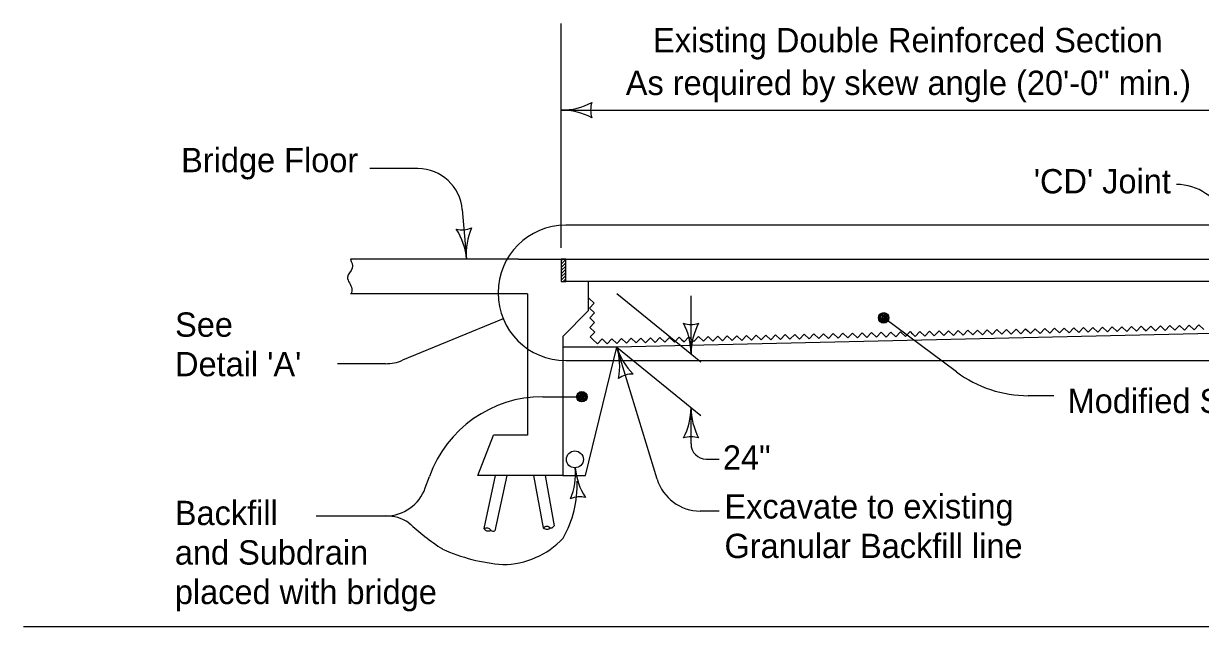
# Model space of a CAD drawing. Extents: x -2134860 to -2124557, y -2139046 to -2137324.
# Drawn here: x -2131334 to -2130560, y -2138041 to -2137644 of the extents above; entities that cross this region are included whole.
import ezdxf

# ---------------------------------------------------------------- set-up
doc = ezdxf.new("R2010")
doc.units = 0
for name, color, linetype in [('BridgeSuperStructureExisting', 7, 'Continuous'), ('dsnAlignmentCurveData', 7, 'Continuous'), ('dsnStdLabel', 7, 'Continuous')]:
    doc.layers.add(name, color=color, linetype=linetype)

msp = doc.modelspace()

# ---------------------------------------------------------------- linework, layer by layer
at = {"layer": 'BridgeSuperStructureExisting'}
for p, q in [((-2130980.5, -2137791.68), (-2130980.5, -2137644.1)), ((-2130980.5, -2137701.07), (-2130532.03, -2137701.07)), ((-2131074.8, -2137739.48), (-2131106.53, -2137739.48)), ((-2131045.68, -2137766.6), (-2131042.85, -2137799.1)), ((-2130172.43, -2137776.83), (-2130977.53, -2137776.83)), ((-2131008.72, -2137799.1), (-2131119.33, -2137799.1)), ((-2131008.72, -2137799.1), (-2130980.5, -2137799.1)), ((-2130980.5, -2137799.1), (-2130980.5, -2137813.91)), ((-2130977.53, -2137799.1), (-2130980.5, -2137799.1)), ((-2130980.5, -2137802.48), (-2130977.53, -2137799.51)), ((-2130980.5, -2137800.38), (-2130979.63, -2137799.51)), ((-2130977.53, -2137799.51), (-2130980.5, -2137799.51)), ((-2130977.53, -2137799.1), (-2129819.23, -2137799.1)), ((-2130980.5, -2137804.58), (-2130977.53, -2137801.61)), ((-2130980.5, -2137806.68), (-2130977.53, -2137803.71)), ((-2130980.5, -2137808.78), (-2130977.53, -2137805.81)), ((-2130980.5, -2137810.88), (-2130977.53, -2137807.91)), ((-2130980.5, -2137812.98), (-2130977.53, -2137810.01)), ((-2130980.5, -2137813.91), (-2130977.53, -2137813.91)), ((-2130979.33, -2137813.91), (-2130977.53, -2137812.11)), ((-2129819.23, -2137813.95), (-2130977.53, -2137813.95)), ((-2130962.68, -2137813.91), (-2130962.68, -2137833.26)), ((-2131002.78, -2137822.01), (-2131119.33, -2137822.01)), ((-2131002.78, -2137822.01), (-2131002.78, -2137914.93)), ((-2130943.89, -2137821.73), (-2130888.61, -2137866.75)), ((-2130895.08, -2137861.48), (-2130895.08, -2137823.29)), ((-2129819.23, -2137831.61), (-2130943.89, -2137857.02)), ((-2131018.7, -2137838.39), (-2131084.89, -2137865.74)), ((-2130962.68, -2137833.26), (-2130979.48, -2137850.06)), ((-2130720.28, -2137873.45), (-2130768.25, -2137837.85)), ((-2130979.48, -2137850.06), (-2130979.48, -2137941.66)), ((-2130943.89, -2137857.02), (-2130979.48, -2137857.02)), ((-2130964.58, -2137941.66), (-2130943.89, -2137857.02)), ((-2130943.89, -2137857.02), (-2130888.61, -2137902.04)), ((-2130917.41, -2137943.9), (-2130943.89, -2137857.02)), ((-2131096.23, -2137867.99), (-2131127.79, -2137867.99)), ((-2130977.53, -2137865.93), (-2130172.43, -2137865.93)), ((-2130656.21, -2137889.05), (-2130673.08, -2137889.05)), ((-2130895.08, -2137920.77), (-2130895.08, -2137896.77)), ((-2131035.45, -2137941.66), (-2131025.17, -2137914.93)), ((-2131002.78, -2137914.93), (-2131025.17, -2137914.93)), ((-2130885.08, -2137930.77), (-2130876.52, -2137930.77)), ((-2130979.48, -2137941.66), (-2131035.45, -2137941.66)), ((-2131023.98, -2137941.66), (-2131031.49, -2137976.48)), ((-2131016.39, -2137941.66), (-2131024.24, -2137978.05)), ((-2130998.72, -2137941.66), (-2130992.42, -2137976)), ((-2130991.17, -2137941.66), (-2130985.11, -2137974.66)), ((-2130979.48, -2137941.66), (-2130964.58, -2137941.66)), ((-2130889, -2137964.94), (-2130876.52, -2137964.94))]:
    msp.add_line(p, q, dxfattribs=at)
for points in [[(-2130959.72, -2137852.08), (-2130961.45, -2137850.42), (-2130958.36, -2137847.18), (-2130961.6, -2137844.08), (-2130958.51, -2137840.84), (-2130961.75, -2137837.75), (-2130958.66, -2137834.51), (-2130961.9, -2137831.42), (-2130958.8, -2137828.17), (-2130962.04, -2137825.08), (-2130961.9, -2137824.93)], [(-2130767.99, -2137834.67), (-2130769.15, -2137835.19), (-2130770.97, -2137835.76), (-2130771.33, -2137837.6), (-2130771.08, -2137839.22), (-2130769.91, -2137840.72), (-2130768.18, -2137840.57), (-2130766.36, -2137840.31), (-2130765.48, -2137838.86), (-2130765.32, -2137837.33), (-2130766.4, -2137835.32), (-2130767.73, -2137835.15), (-2130769.55, -2137835.62), (-2130771.04, -2137836.78), (-2130770.99, -2137838.51), (-2130769.83, -2137839.9), (-2130768.2, -2137840.06), (-2130766.37, -2137839.7), (-2130766.09, -2137838.68), (-2130765.73, -2137837.44), (-2130766.59, -2137835.94), (-2130767.91, -2137835.97), (-2130769.43, -2137836.22), (-2130770.53, -2137837.07), (-2130769.97, -2137838.58), (-2130768.83, -2137839.47), (-2130767.29, -2137839.52), (-2130766.91, -2137838.7), (-2130766.43, -2137837.76), (-2130767.18, -2137836.57), (-2130768.3, -2137836.29), (-2130769.31, -2137836.83), (-2130769.38, -2137837.95), (-2130768.85, -2137838.75), (-2130767.82, -2137839.03), (-2130767.32, -2137838.6), (-2130767.03, -2137837.99), (-2130767.57, -2137837.08), (-2130768.29, -2137836.9), (-2130768.99, -2137837.33), (-2130768.87, -2137837.94), (-2130768.35, -2137838.33), (-2130767.64, -2137838.31), (-2130767.65, -2137837.8), (-2130768.27, -2137837.51)], [(-2130825.23, -2137850.23), (-2130823.61, -2137851.78), (-2130820.51, -2137848.54), (-2130817.27, -2137851.62), (-2130814.18, -2137848.39), (-2130810.94, -2137851.47), (-2130807.85, -2137848.24), (-2130804.6, -2137851.33), (-2130801.51, -2137848.09), (-2130798.27, -2137851.18), (-2130795.18, -2137847.94), (-2130791.94, -2137851.03), (-2130788.84, -2137847.79), (-2130785.6, -2137850.88), (-2130782.51, -2137847.64), (-2130779.27, -2137850.74), (-2130776.18, -2137847.5), (-2130772.93, -2137850.59), (-2130769.84, -2137847.35), (-2130766.6, -2137850.44), (-2130763.51, -2137847.2), (-2130760.27, -2137850.29), (-2130757.17, -2137847.05), (-2130753.93, -2137850.14), (-2130750.84, -2137846.9), (-2130749.22, -2137848.45)], [(-2130749.22, -2137848.44), (-2130747.6, -2137849.99), (-2130744.51, -2137846.75), (-2130741.26, -2137849.84), (-2130738.17, -2137846.6), (-2130734.93, -2137849.69), (-2130731.83, -2137846.45), (-2130728.59, -2137849.54), (-2130725.5, -2137846.3), (-2130722.26, -2137849.39), (-2130719.17, -2137846.15), (-2130715.93, -2137849.25), (-2130712.83, -2137846), (-2130709.59, -2137849.1), (-2130706.5, -2137845.86), (-2130703.26, -2137848.95), (-2130700.17, -2137845.71), (-2130696.92, -2137848.8), (-2130693.83, -2137845.56), (-2130690.59, -2137848.65), (-2130687.5, -2137845.41), (-2130684.26, -2137848.5), (-2130681.16, -2137845.26), (-2130677.92, -2137848.35), (-2130674.82, -2137845.11), (-2130673.21, -2137846.66)], [(-2130673.21, -2137846.65), (-2130671.59, -2137848.2), (-2130668.5, -2137844.96), (-2130665.25, -2137848.05), (-2130662.16, -2137844.81), (-2130658.92, -2137847.91), (-2130655.83, -2137844.66), (-2130652.59, -2137847.76), (-2130649.49, -2137844.51), (-2130646.25, -2137847.61), (-2130643.16, -2137844.37), (-2130639.91, -2137847.46), (-2130636.83, -2137844.22), (-2130633.58, -2137847.31), (-2130630.49, -2137844.07), (-2130627.25, -2137847.17), (-2130624.15, -2137843.92), (-2130620.91, -2137847.02), (-2130617.82, -2137843.77), (-2130614.58, -2137846.86), (-2130611.49, -2137843.63), (-2130608.24, -2137846.72), (-2130605.15, -2137843.48), (-2130601.91, -2137846.57), (-2130598.82, -2137843.33), (-2130597.19, -2137844.88)], [(-2130597.19, -2137844.9), (-2130595.57, -2137846.45), (-2130592.48, -2137843.2), (-2130589.24, -2137846.3), (-2130586.15, -2137843.06), (-2130582.91, -2137846.14), (-2130579.81, -2137842.9), (-2130576.57, -2137846), (-2130573.48, -2137842.75), (-2130570.24, -2137845.85), (-2130567.15, -2137842.61), (-2130563.9, -2137845.7), (-2130560.81, -2137842.46), (-2130557.57, -2137845.55)], [(-2130959.94, -2137851.95), (-2130959.87, -2137851.87), (-2130956.63, -2137854.97), (-2130953.53, -2137851.72), (-2130950.29, -2137854.82), (-2130947.2, -2137851.58), (-2130943.96, -2137854.67), (-2130940.87, -2137851.43), (-2130937.62, -2137854.52), (-2130934.53, -2137851.28), (-2130931.29, -2137854.37), (-2130928.2, -2137851.13), (-2130924.96, -2137854.22), (-2130921.86, -2137850.98), (-2130918.62, -2137854.07), (-2130915.53, -2137850.83), (-2130912.29, -2137853.93), (-2130909.19, -2137850.69), (-2130905.95, -2137853.78), (-2130902.86, -2137850.54), (-2130901.24, -2137852.08)], [(-2130901.24, -2137852.01), (-2130899.62, -2137853.56), (-2130896.53, -2137850.32), (-2130893.28, -2137853.42), (-2130890.19, -2137850.17), (-2130886.95, -2137853.26), (-2130883.86, -2137850.03), (-2130880.62, -2137853.11), (-2130877.52, -2137849.87), (-2130874.28, -2137852.96), (-2130871.19, -2137849.72), (-2130867.95, -2137852.82), (-2130864.86, -2137849.58), (-2130861.61, -2137852.67), (-2130858.52, -2137849.43), (-2130855.28, -2137852.52), (-2130852.19, -2137849.28), (-2130848.95, -2137852.37), (-2130845.85, -2137849.13), (-2130842.61, -2137852.23), (-2130839.52, -2137848.99), (-2130836.27, -2137852.08), (-2130833.18, -2137848.84), (-2130829.94, -2137851.93), (-2130826.85, -2137848.69), (-2130825.23, -2137850.24)], [(-2130967.21, -2137892.91), (-2130966.04, -2137892.38), (-2130964.22, -2137891.82), (-2130963.87, -2137889.97), (-2130964.12, -2137888.35), (-2130965.28, -2137886.86), (-2130967.01, -2137887.01), (-2130968.84, -2137887.26), (-2130969.71, -2137888.72), (-2130969.87, -2137890.25), (-2130968.79, -2137892.26), (-2130967.46, -2137892.42), (-2130965.64, -2137891.96), (-2130964.15, -2137890.8), (-2130964.2, -2137889.07), (-2130965.36, -2137887.68), (-2130967, -2137887.52), (-2130968.82, -2137887.87), (-2130969.09, -2137888.9), (-2130969.47, -2137890.14), (-2130968.61, -2137891.64), (-2130967.28, -2137891.6), (-2130965.76, -2137891.35), (-2130964.67, -2137890.51), (-2130965.22, -2137888.99), (-2130966.37, -2137888.11), (-2130967.9, -2137888.06), (-2130968.28, -2137888.88), (-2130968.76, -2137889.81), (-2130968.02, -2137891.01), (-2130966.89, -2137891.29), (-2130965.88, -2137890.75), (-2130965.82, -2137889.62), (-2130966.35, -2137888.82), (-2130967.38, -2137888.55), (-2130967.87, -2137888.97), (-2130968.16, -2137889.59), (-2130967.62, -2137890.49), (-2130966.9, -2137890.67), (-2130966.2, -2137890.25), (-2130966.32, -2137889.64), (-2130966.85, -2137889.24), (-2130967.56, -2137889.27), (-2130967.54, -2137889.77), (-2130966.92, -2137890.06)]]:
    msp.add_lwpolyline(points, dxfattribs=at)
for centre, radius in [((-2130768.25, -2137837.85), 3.46), ((-2130966.94, -2137889.73), 3.46), ((-2130971.53, -2137930.97), 5.57)]:
    msp.add_circle(centre, radius, dxfattribs=at)
for centre, radius, start, end in [((-2130980.5, -2137658.33), 42.75, 270, 298.07249), ((-2130944.66, -2137701.08), 16.51, 162.26665, 197.73335), ((-2130980.5, -2137743.83), 42.75, 61.92751, 90), ((-2131075.26, -2137769.18), 29.7, 4.96959, 89.10647), ((-2130575.56, -2137784.7), 34.65, 22.59071, 90), ((-2130977.53, -2137821.38), 44.55, 90, 269.99985), ((-2131045.96, -2137763.4), 16.51, 257.23564, 292.70234), ((-2131085.44, -2137802.81), 42.75, 4.96899, 33.04148), ((-2131000.26, -2137795.4), 42.75, 156.8965, 184.96899), ((-2130895.08, -2137825.64), 16.51, 252.26665, 287.73335), ((-2130937.82, -2137861.48), 42.75, 360, 28.07249), ((-2130852.33, -2137861.48), 42.75, 151.92751, 180), ((-2130903.01, -2137844.56), 42.75, 196.9537, 225.02619), ((-2130984.79, -2137869.49), 42.75, 348.88121, 16.9537), ((-2130903.01, -2137844.56), 42.75, 196.9537, 225.02619), ((-2130984.79, -2137869.49), 42.75, 348.88121, 16.9537), ((-2131096.23, -2137838.29), 29.7, 270, 292.44963), ((-2130933.44, -2137891.31), 16.51, 89.22034, 124.68705), ((-2130933.44, -2137891.31), 16.51, 89.22034, 124.68705), ((-2130673.08, -2137809.85), 79.2, 233.42435, 270), ((-2130992.7, -2137968.93), 79.2, 90, 160.30121), ((-2130937.82, -2137896.77), 42.75, 331.92751, 360), ((-2130852.33, -2137896.77), 42.75, 180, 208.07249), ((-2130895.08, -2137932.62), 16.51, 72.26665, 107.73335), ((-2130885.08, -2137920.77), 10, 180, 270), ((-2131013.62, -2137940.42), 42.5, 337.1139, 5.18639), ((-2130928.97, -2137932.74), 42.5, 185.18639, 213.25888), ((-2130889, -2137935.25), 29.7, 196.95347, 270), ((-2131096.07, -2137940.45), 27.72, 270, 340.30186), ((-2130968.08, -2137972.07), 16.42, 77.45304, 112.91974), ((-2131096.07, -2137995.89), 27.72, 56.82483, 90)]:
    msp.add_arc(centre, radius, start, end, dxfattribs=at)
for points in [[(-2131119.33, -2137799.1), (-2131118.15, -2137805.06), (-2131121.15, -2137811.07), (-2131118.38, -2137818.69), (-2131118.82, -2137822.01)], [(-2131031.49, -2137976.48), (-2131028.41, -2137976.14), (-2131026.65, -2137977.84), (-2131024.24, -2137978.05)], [(-2131031.49, -2137976.48), (-2131029.38, -2137977.96), (-2131026.95, -2137977.78)], [(-2130992.42, -2137976), (-2130989.64, -2137974.86), (-2130986.85, -2137976.08), (-2130985.11, -2137974.66)], [(-2130992.42, -2137976), (-2130989.71, -2137976.93), (-2130987.64, -2137976.08)]]:
    msp.add_spline(points, degree=3, dxfattribs=at)
at = {"layer": 'dsnAlignmentCurveData'}
msp.add_line((-2131334.44, -2138040.95), (-2128199.45, -2138040.95), dxfattribs=at)
at = {"layer": 'dsnStdLabel'}
for p, q in [((-2130977.53, -2137813.91), (-2130977.53, -2137799.11)), ((-2130992.7, -2137889.73), (-2130966.94, -2137889.73)), ((-2131069.98, -2137949.79), (-2131067.27, -2137942.23)), ((-2131141.79, -2137968.17), (-2131096.08, -2137968.17))]:
    msp.add_line(p, q, dxfattribs=at)
for centre, radius, start, end in [((-2131041.33, -2137947.81), 71.28, 330.50921, 2.05109), ((-2130969.63, -2137852.76), 163.6, 227.14423, 236.99423), ((-2131019.31, -2137945.22), 54.97, 270.33247, 316.71985), ((-2131009.79, -2137882.08), 118.47, 245.59148, 265.54605)]:
    msp.add_arc(centre, radius, start, end, dxfattribs=at)

# ---------------------------------------------------------------- texts
for s, p in [('Existing Double Reinforced Section', (-2130920.04, -2137663.02)), ('As required by skew angle (20\'-0" min.)', (-2130938.02, -2137691.13)), ('Bridge Floor', (-2131230.69, -2137741.95)), ("'CD' Joint", (-2130669.44, -2137755.9)), ('See', (-2131234.69, -2137850.25)), ("Detail 'A'", (-2131234.69, -2137876.25)), ('Modified Subbase', (-2130647.18, -2137900.49)), ('24"', (-2130874.09, -2137937.77)), ('Excavate to existing', (-2130873.05, -2137969.91)), ('Backfill', (-2131234.85, -2137974.23)), ('Granular Backfill line', (-2130873.05, -2137995.91)), ('and Subdrain', (-2131234.85, -2138000.23)), ('placed with bridge', (-2131234.85, -2138026.23))]:
    msp.add_text(s, height=16, dxfattribs=at).set_placement(p)

doc.saveas('drawing.dxf')
